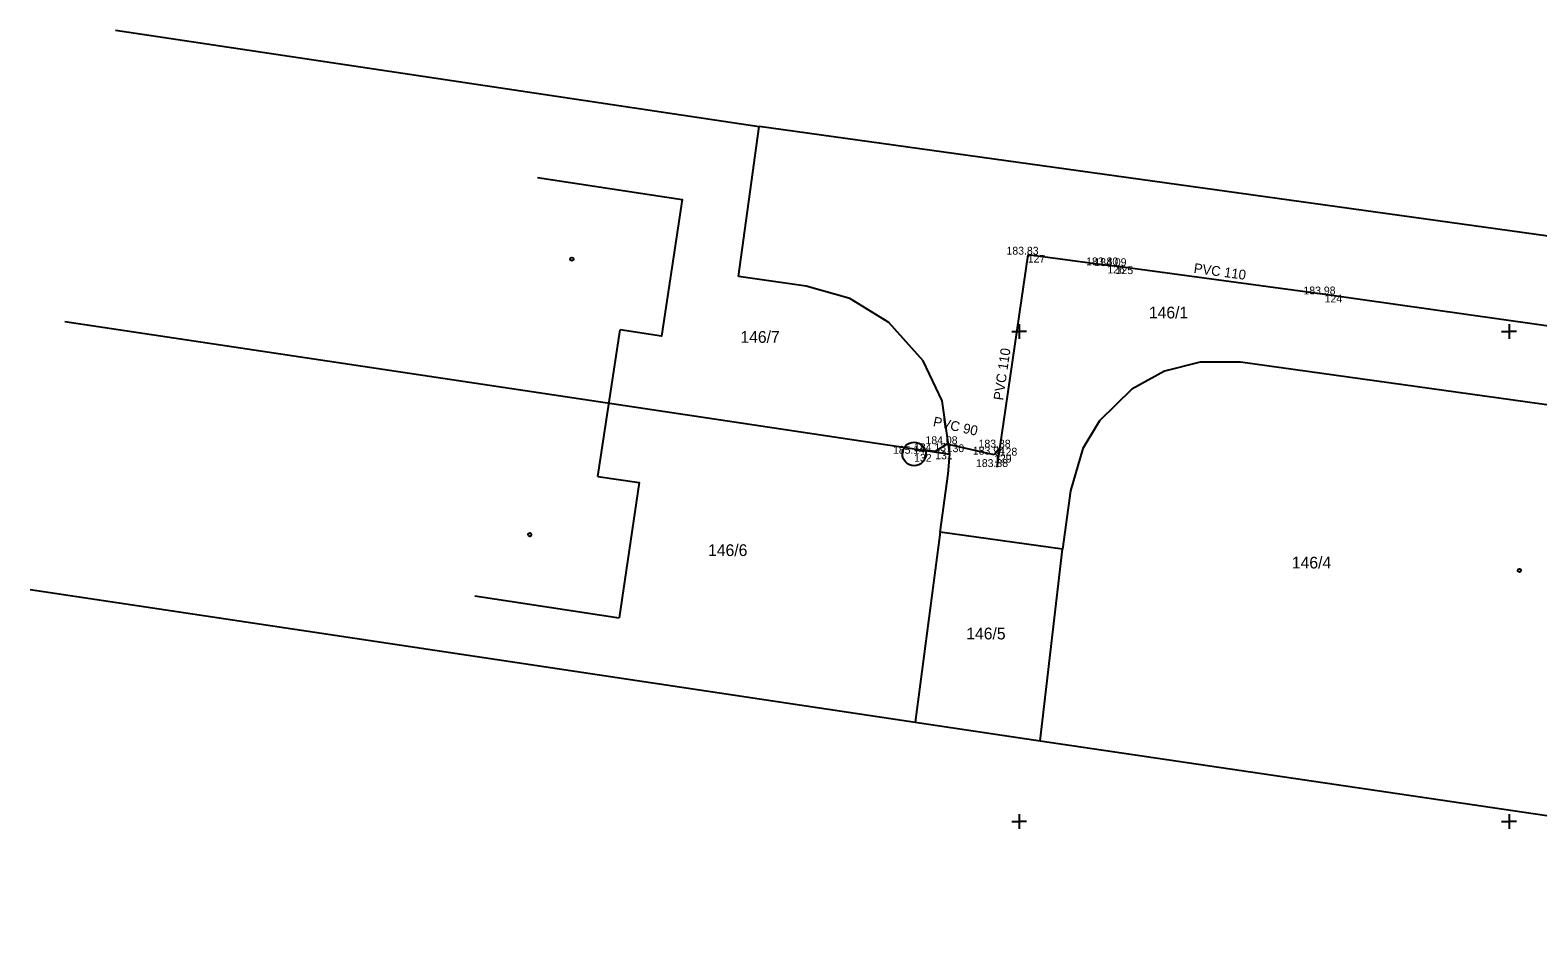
# Model space of a CAD drawing. Extents: x -598400 to -598043, y -1172615 to -1172551.
# Drawn here: x -598400.5 to -598323.5, y -1172605.3 to -1172559.6 of the extents above; entities that cross this region are included whole.
import ezdxf

# ---------------------------------------------------------------- set-up
doc = ezdxf.new("R2010")
doc.units = 0
for name, color, linetype in [('20', 7, 'Continuous'), ('21', 7, 'Continuous'), ('22', 7, 'Continuous'), ('25', 7, 'Continuous'), ('49', 7, 'Continuous'), ('62', 7, 'Continuous')]:
    doc.layers.add(name, color=color, linetype=linetype)

# ---------------------------------------------------------------- blocks, each defined once
blk = doc.blocks.new('POINT_DISPLAY')
blk.add_line((0, 0), (0, 0))
blk = doc.blocks.new('300')
at = {"layer": '62'}
for p, q in [((-1.5, 0), (0, 0)), ((0, 1.5), (0, -1.5)), ((1.5, 0), (0, 0))]:
    blk.add_line(p, q, dxfattribs=at)
blk = doc.blocks.new('299')
at = {"layer": '62', "xscale": 0.5, "yscale": 0.5}
blk.add_blockref('300', (0, 0), dxfattribs=at)
blk = doc.blocks.new('6$200')
at = {"layer": '25'}
blk.add_circle((0, 0), 1, dxfattribs=at)
blk = doc.blocks.new('4$020')
at = {"layer": '49'}
blk.add_circle((0, 0), 0.175, dxfattribs=at)

msp = doc.modelspace()

# ---------------------------------------------------------------- linework, layer by layer
at = {"layer": '20'}
for p, q in [((-598396.13, -1172559.618), (-598363.28, -1172564.54)), ((-598364.34, -1172572.19), (-598363.28, -1172564.54)), ((-598280.714, -1172576.008), (-598363.28, -1172564.54)), ((-598398.72, -1172574.48), (-598353.54, -1172581.25)), ((-598400.49, -1172588.17), (-598355.31, -1172594.94))]:
    msp.add_line(p, q, dxfattribs=at)
for points in [[(-598354.04, -1172585.24), (-598353.63, -1172582.26), (-598353.54, -1172581.25), (-598353.94, -1172578.54), (-598354.9, -1172576.49), (-598356.65, -1172574.53), (-598358.64, -1172573.31), (-598360.87, -1172572.68), (-598364.34, -1172572.19)], [(-598313.07, -1172580.13), (-598338.7, -1172576.57), (-598340.77, -1172576.56), (-598342.58, -1172577.03), (-598344.26, -1172577.94), (-598345.9, -1172579.55), (-598346.76, -1172580.97), (-598347.39, -1172583.13), (-598347.8, -1172586.1), (-598354.04, -1172585.24)], [(-598354.04, -1172585.24), (-598355.31, -1172594.94), (-598348.93, -1172595.88), (-598347.8, -1172586.1)], [(-598348.93, -1172595.88), (-598316.14, -1172600.72), (-598284.96, -1172605.33)]]:
    msp.add_lwpolyline(points, dxfattribs=at)
at = {"layer": '25'}
for p, q in [((-598349.568, -1172571.085), (-598351.137, -1172581.923)), ((-598345.501, -1172571.63), (-598349.568, -1172571.085)), ((-598345.079, -1172571.668), (-598345.501, -1172571.63)), ((-598334.409, -1172573.113), (-598345.079, -1172571.668)), ((-598320.233, -1172575.115), (-598334.409, -1172573.113)), ((-598354.291, -1172581.12), (-598355.341, -1172581.017)), ((-598353.702, -1172580.755), (-598354.291, -1172581.12)), ((-598351.286, -1172581.29), (-598353.702, -1172580.755)), ((-598350.993, -1172580.931), (-598351.286, -1172581.29))]:
    msp.add_line(p, q, dxfattribs=at)
at = {"layer": '49'}
for p, q in [((-598371.505, -1172582.392), (-598370.369, -1172574.917)), ((-598377.793, -1172588.486), (-598370.419, -1172589.604))]:
    msp.add_line(p, q, dxfattribs=at)
for points in [[(-598374.586, -1172567.137), (-598367.212, -1172568.255), (-598368.27, -1172575.235), (-598370.369, -1172574.917)], [(-598371.505, -1172582.392), (-598369.406, -1172582.71), (-598370.419, -1172589.604)]]:
    msp.add_lwpolyline(points, dxfattribs=at)

# ---------------------------------------------------------------- block references
at = {"layer": '22'}
for p in [(-598363.28, -1172564.54), (-598349.568, -1172571.085), (-598345.501, -1172571.63), (-598345.079, -1172571.668), (-598364.34, -1172572.19), (-598360.87, -1172572.68), (-598358.64, -1172573.31), (-598334.409, -1172573.113), (-598398.72, -1172574.48), (-598356.65, -1172574.53), (-598354.9, -1172576.49), (-598342.58, -1172577.03), (-598340.77, -1172576.56), (-598338.7, -1172576.57), (-598344.26, -1172577.94), (-598353.94, -1172578.54), (-598345.9, -1172579.55), (-598353.702, -1172580.755), (-598350.993, -1172580.931), (-598346.76, -1172580.97), (-598355.365, -1172581.247), (-598354.291, -1172581.12), (-598353.54, -1172581.25), (-598351.286, -1172581.29), (-598353.63, -1172582.26), (-598347.39, -1172583.13), (-598354.04, -1172585.24), (-598347.8, -1172586.1), (-598355.31, -1172594.94), (-598348.93, -1172595.88)]:
    msp.add_blockref('POINT_DISPLAY', p, dxfattribs=at)
at = {"layer": '25', "xscale": 0.6000009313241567, "yscale": 0.6000009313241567, "rotation": -90.00000000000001}
msp.add_blockref('6$200', (-598355.365, -1172581.247), dxfattribs=at)
at = {"layer": '49', "xscale": 0.5, "yscale": 0.5}
for p in [(-598372.837, -1172571.3), (-598374.987, -1172585.365), (-598324.468, -1172587.19)]:
    msp.add_blockref('4$020', p, dxfattribs=at)
at = {"layer": '62', "xscale": 0.5, "yscale": 0.5}
for p in [(-598350, -1172575), (-598325, -1172575), (-598350, -1172600), (-598325, -1172600)]:
    msp.add_blockref('299', p, dxfattribs=at)

# ---------------------------------------------------------------- texts
at = {"layer": '20'}
for s, height, p in [('127', 0.4, (-598349.568, -1172571.485)), ('126', 0.4, (-598345.501, -1172572.03)), ('125', 0.4, (-598345.079, -1172572.068)), ('124', 0.4, (-598334.409, -1172573.513)), ('146/1', 0.6, (-598343.383, -1172574.33)), ('146/7', 0.6, (-598364.235, -1172575.575)), ('130', 0.4, (-598353.702, -1172581.155)), ('128', 0.4, (-598350.993, -1172581.331)), ('132', 0.4, (-598355.365, -1172581.647)), ('131', 0.4, (-598354.291, -1172581.52)), ('129', 0.4, (-598351.286, -1172581.69)), ('146/6', 0.6, (-598365.885, -1172586.457)), ('146/4', 0.6, (-598336.085, -1172587.091)), ('146/5', 0.6, (-598352.705, -1172590.711))]:
    msp.add_text(s, height=height, dxfattribs=at).set_placement(p)
at = {"layer": '21'}
for s, p in [('183.83', (-598350.651, -1172571.075)), ('183.80', (-598346.584, -1172571.62)), ('184.09', (-598346.162, -1172571.658)), ('183.98', (-598335.492, -1172573.103)), ('185.14', (-598356.448, -1172581.237)), ('184.13', (-598355.374, -1172581.11)), ('184.08', (-598354.785, -1172580.745)), ('183.94', (-598352.369, -1172581.28)), ('183.88', (-598352.076, -1172580.921)), ('183.88', (-598352.208, -1172581.914))]:
    msp.add_text(s, height=0.4, dxfattribs=at).set_placement(p)
at = {"layer": '25'}
for s, rotation, p in [('PVC 110', 352.25036, (-598341.115, -1172572.002)), ('PVC 110', 81.881, (-598350.822, -1172578.533)), ('PVC 90', 347.40951, (-598354.431, -1172579.82))]:
    msp.add_text(s, height=0.5, rotation=rotation, dxfattribs=at).set_placement(p)

doc.saveas('drawing.dxf')
